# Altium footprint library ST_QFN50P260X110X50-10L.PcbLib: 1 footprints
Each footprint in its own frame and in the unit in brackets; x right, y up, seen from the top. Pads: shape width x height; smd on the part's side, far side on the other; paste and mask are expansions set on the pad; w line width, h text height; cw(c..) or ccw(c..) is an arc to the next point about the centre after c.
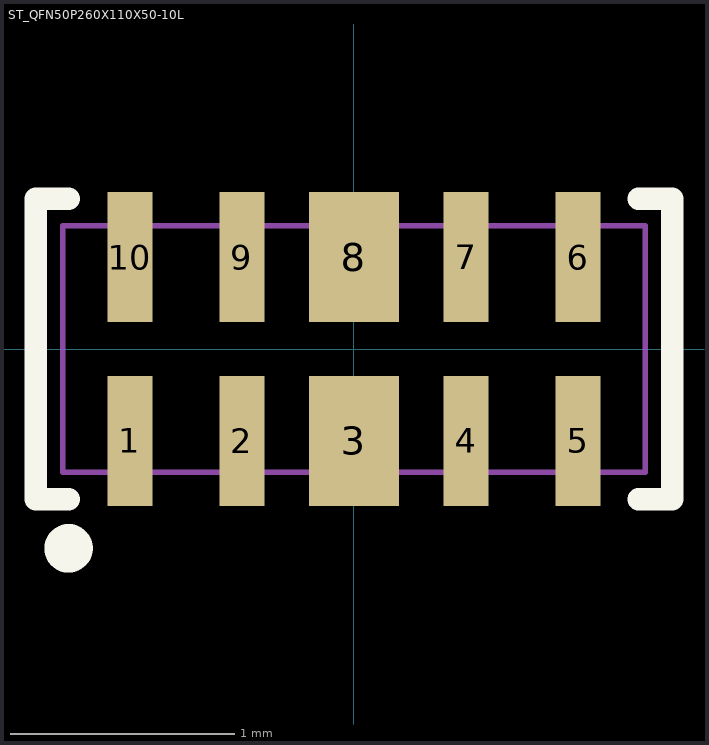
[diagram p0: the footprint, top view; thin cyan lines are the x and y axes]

## ST_QFN50P260X110X50-10L [mm] "ST_QFN50P260X110X50-10L"
pads (10):
  rect 0.2x0.58 smd paste-20 mask+0.05: 1(-1,-0.41) 2(-0.5,-0.41) 4(0.5,-0.41) 7(0.5,0.41) 9(-0.5,0.41) 10(-1,0.41)
  rect 0.4x0.58 smd paste-20 mask+0.05: 3(0,-0.41) 8(0,0.41)
  rect 0.2x0.58 smd mask+0.05: 5(1,-0.41) 6(1,0.41)
Top Overlay:
  circle w0.15: c-1.274,-0.889 r0.033
  lines w0.1: -1.272,-0.67 -1.42,-0.67 -1.42,0.67 -1.272,0.67 ; 1.27,-0.67 1.42,-0.67 1.42,0.67 1.27,0.67
Top Paste:
  rectangle: 0.405,-0.685 0.595,-0.135
  rectangle: -0.19,-0.685 0.19,-0.135
  rectangle: -0.595,-0.685 -0.405,-0.135
  rectangle: -1.095,-0.685 -0.905,-0.135
  rectangle: 0.405,0.135 0.595,0.685
  rectangle: -0.19,0.135 0.19,0.685
  rectangle: -0.595,0.135 -0.405,0.685
  rectangle: -1.095,0.135 -0.905,0.685
Mechanical 5:
  text "3" at -0.035,-0.87 h0.05
  text "8" at 0.025,0.785 h0.05
  text "1" at -1.035,-0.87 h0.05
  text "2" at -0.535,-0.87 h0.05
  text "4" at 0.465,-0.87 h0.05
  text "5" at 0.965,-0.87 h0.05
  text "6" at 1.025,0.785 h0.05
  text "7" at 0.525,0.785 h0.05
  text "9" at -0.475,0.785 h0.05
  text "10" at -1.015,0.785 h0.05
Mechanical 6:
  lines w0.025: -1.3,-0.55 1.3,-0.55 1.3,0.55 -1.3,0.55 -1.3,-0.55
Assembly:
  lines w0.025: -1.3,-0.55 -1.3,0.55 1.3,0.55 1.3,-0.55 -1.3,-0.55
3D body: height 0.5, standoff 0, extent -1.3,-0.55 1.3,0.55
